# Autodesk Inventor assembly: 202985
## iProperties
Created: 2007-12
Part Number: 202985
Document SubType Name: Assembly
Designer: MM
Mass: 2360.19 g
Surface Area: 15768.9 cm^2
Volume: 1841.17 cm^3
Density: 1.2819 g/cm^3
Description: LOWER FULL ASSEMBLY
Component Category: Lower Component
Author: MM
